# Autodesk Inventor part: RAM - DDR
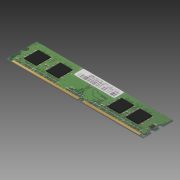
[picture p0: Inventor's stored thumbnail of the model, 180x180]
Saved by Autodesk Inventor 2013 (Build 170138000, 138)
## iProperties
Company: Autodesk Inc.
Created: 2005-12
Part Number: RAM - DDR
Document SubType Name: Modeling
Designer: Autodesk Inc.
Density: 1 g/cm^3
Mass: 4.45281 g
Surface Area: 81.6838 cm^2
Volume: 4.45281 cm^3
Material: Allgemein
Title: Personzl Computer
Author: Autodesk Inc.
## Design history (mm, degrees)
sketch "Sketch1"
  geometry: L1 (0, 34.8)-(0, -5.8) reference; L2 (-93.1, 0)-(93.1, 0) reference; L3 (-66.5, 0)-(66.5, 0); L4 (66.5, 0)-(66.5, 29); L5 (66.5, 29)-(-66.5, 29); L6 (-66.5, 29)-(-66.5, 0)
  constraints: 8 end point, 2 parallel, 1 horizontal, 1 perpendicular, 1 point on line, 1 other
  dimensions: "d0" = 133 distance of L4.end L5.end; "d1" = 29 distance of L5.end L3.start
extrude "Extrusion1" new body sketch "Sketch1" distance "d2" = 1; taper "d3" = 0 deg
sketch "Sketch3"
  geometry: L1 (-66.5, 29.39)-(66.5, 29.39); L2 (66.5, 29.39)-(66.5, 0); L3 (66.5, 0)-(-66.5, 0); L4 (-66.5, 0)-(-66.5, 29.39); 1 other entity
  constraints: 2 other
  dimensions: "d9" = 133 distance of L1.start L1.end
feature "Decal1" sketch "Sketch3"
sketch "Sketch4"
  geometry: L1 (-66.5, 29.39)-(66.5, 29.39); L2 (66.5, 29.39)-(66.5, 0); L3 (66.5, 0)-(-66.5, 0); L4 (-66.5, 0)-(-66.5, 29.39); 1 other entity
  constraints: 2 other
  dimensions: "d11" = 133 distance of L1.start L1.end
feature "Decal2" sketch "Sketch4"
sketch "Sketch5"
  geometry: L1 (-66.5, 0)-(-66.5, 29) reference; L2 (66.5, 29)-(66.5, 0) reference; L3 (-66.5, 19.147)-(-65.582, 19.147); L4 (-65.582, 19.147)-(-65.582, 15.286); L5 (-65.582, 15.286)-(-66.5, 15.286); L6 (-66.5, 15.286)-(-66.5, 19.147); L7 (-66.5, 11.286)-(-65.582, 11.286); L8 (-65.582, 11.286)-(-65.582, 7.425); L9 (-65.582, 7.425)-(-66.5, 7.425); L10 (-66.5, 7.425)-(-66.5, 11.286); L11 (66.5, 19.424)-(65.139, 19.424); L12 (65.139, 19.424)-(65.139, 15.625); L13 (65.139, 15.625)-(66.5, 15.625); L14 (66.5, 15.625)-(66.5, 19.424); L15 (66.5, 11.626)-(65.339, 11.626); L16 (65.339, 11.626)-(65.339, 7.826); L17 (65.339, 7.826)-(66.5, 7.826); L18 (66.5, 7.826)-(66.5, 11.626); C1 r 1.5 at (-64.465, 1.845); C2 r 1.5 at (64.823, 1.845); 4 further points
  constraints: 32 end point, 8 parallel, 4 horizontal, 4 midpoint, 4 perpendicular, 4 point on line, 4 vertical alignment, 2 centre point, 1 equal radius, 1 horizontal alignment, 8 other
  dimensions: "d12" = 3 diameter of C1
extrude "Extrusion2" cut sketch "Sketch5" stored distance "d13" = 1.5; taper "d14" = 0 deg
sketch "Sketch6"
  geometry: L1 (66.5, 0)-(-66.5, 0) reference; L2 (3.433, 2.75)-(4.933, 2.75); L3 (4.933, 2.75)-(4.933, 0); L4 (4.933, 0)-(3.433, 0); L5 (3.433, 0)-(3.433, 2.75); 1 further point
  constraints: 8 end point, 2 parallel, 1 horizontal, 1 horizontal alignment, 1 midpoint, 1 perpendicular, 1 point on line, 2 other
  dimensions: "d15" = 1.5 distance between parallel lines of L3 L5; "d16" = 2.75 distance between parallel lines of L1 L2
extrude "Extrusion3" cut sketch "Sketch6" stored distance "d17" = 1.5; taper "d18" = 0 deg
sketch "Sketch7"
  geometry: L1 (-46.103, 8.366)-(-58.103, 8.366); L2 (-58.103, 8.366)-(-58.103, 22.366); L3 (-58.103, 22.366)-(-46.103, 22.366); L4 (-46.103, 22.366)-(-46.103, 8.366); L5 (-36.73, 22.366)-(-24.73, 22.366); L6 (-24.73, 22.366)-(-24.73, 8.366); L7 (-24.73, 8.366)-(-36.73, 8.366); L8 (-36.73, 8.366)-(-36.73, 22.366); L9 (22.999, 22.366)-(34.999, 22.366); L10 (34.999, 22.366)-(34.999, 8.366); L11 (34.999, 8.366)-(22.999, 8.366); L12 (22.999, 8.366)-(22.999, 22.366); L13 (40.986, 22.366)-(52.986, 22.366); L14 (52.986, 22.366)-(52.986, 8.366); L15 (52.986, 8.366)-(40.986, 8.366); L16 (40.986, 8.366)-(40.986, 22.366)
  constraints: 32 end point, 9 collinear, 8 parallel, 4 horizontal, 4 perpendicular
  dimensions: "d21" = 14 distance of L1.end L2.end; "d22" = 12 distance of L2.end L3.end
extrude "Extrusion4" join sketch "Sketch7" distance "d23" = 0.5; taper "d24" = 0 deg
sketch "Sketch8"
  geometry: L1 (-58.086, 22.482)-(-46.586, 22.482); L2 (-46.586, 22.482)-(-46.586, 8.482); L3 (-46.586, 8.482)-(-58.086, 8.482); L4 (-58.086, 8.482)-(-58.086, 22.482); L5 (-36.84, 22.482)-(-25.34, 22.482); L6 (-25.34, 22.482)-(-25.34, 8.482); L7 (-25.34, 8.482)-(-36.84, 8.482); L8 (-36.84, 8.482)-(-36.84, 22.482); L9 (23.403, 22.245)-(34.903, 22.245); L10 (34.903, 22.245)-(34.903, 8.482); L11 (34.903, 8.482)-(23.403, 8.482); L12 (23.403, 8.482)-(23.403, 22.245); L13 (41.476, 22.138)-(52.976, 22.138); L14 (52.976, 22.138)-(52.976, 8.482); L15 (52.976, 8.482)-(41.476, 8.482); L16 (41.476, 8.482)-(41.476, 22.138)
  constraints: 32 end point, 8 parallel, 4 collinear, 4 horizontal, 4 perpendicular, 3 equal length
  dimensions: "d28" = 11.5 distance of L1.start L1.end; "d29" = 14 distance of L3.end L1.start
extrude "Extrusion5" join sketch "Sketch8" distance "d30" = 0.5; taper "d31" = 0 deg
body "Solid1"
node "Image2"
node "Image3"
